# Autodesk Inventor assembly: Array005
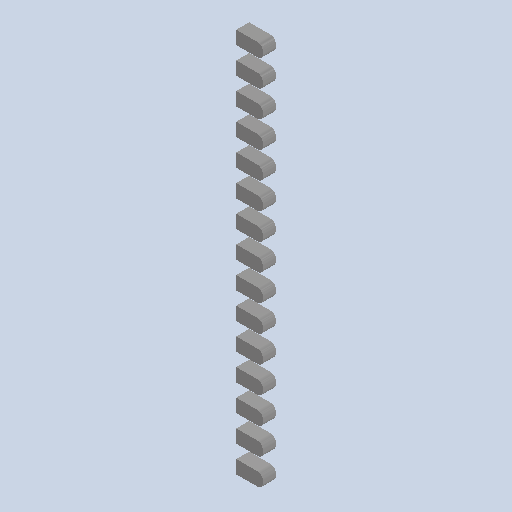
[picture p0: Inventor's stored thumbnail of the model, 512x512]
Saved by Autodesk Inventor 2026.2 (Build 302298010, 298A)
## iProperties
Created: 2026-10
Part Number: Array005
Document SubType Name: Assembly
Designer: mel
Author: mel
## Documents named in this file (16)
- D:\travail\année 2026-2027\1 sti2d IT\poubelle à verre\raspberry-pico-2-microcontroller-rp2350-1.snapshot.5\raspberry_pico_2\raspberry_pico_2\Array005.iam
- D:\travail\année 2026-2027\1 sti2d IT\poubelle à verre\raspberry-pico-2-microcontroller-rp2350-1.snapshot.5\raspberry_pico_2\raspberry_pico_2\Fillet015.ipt
- D:\travail\année 2026-2027\1 sti2d IT\poubelle à verre\raspberry-pico-2-microcontroller-rp2350-1.snapshot.5\raspberry_pico_2\raspberry_pico_2\Fillet016.ipt
- D:\travail\année 2026-2027\1 sti2d IT\poubelle à verre\raspberry-pico-2-microcontroller-rp2350-1.snapshot.5\raspberry_pico_2\raspberry_pico_2\Fillet017.ipt
- D:\travail\année 2026-2027\1 sti2d IT\poubelle à verre\raspberry-pico-2-microcontroller-rp2350-1.snapshot.5\raspberry_pico_2\raspberry_pico_2\Fillet018.ipt
- D:\travail\année 2026-2027\1 sti2d IT\poubelle à verre\raspberry-pico-2-microcontroller-rp2350-1.snapshot.5\raspberry_pico_2\raspberry_pico_2\Fillet019.ipt
- D:\travail\année 2026-2027\1 sti2d IT\poubelle à verre\raspberry-pico-2-microcontroller-rp2350-1.snapshot.5\raspberry_pico_2\raspberry_pico_2\Fillet020.ipt
- D:\travail\année 2026-2027\1 sti2d IT\poubelle à verre\raspberry-pico-2-microcontroller-rp2350-1.snapshot.5\raspberry_pico_2\raspberry_pico_2\Fillet021.ipt
- D:\travail\année 2026-2027\1 sti2d IT\poubelle à verre\raspberry-pico-2-microcontroller-rp2350-1.snapshot.5\raspberry_pico_2\raspberry_pico_2\Fillet022.ipt
- D:\travail\année 2026-2027\1 sti2d IT\poubelle à verre\raspberry-pico-2-microcontroller-rp2350-1.snapshot.5\raspberry_pico_2\raspberry_pico_2\Fillet023.ipt
- D:\travail\année 2026-2027\1 sti2d IT\poubelle à verre\raspberry-pico-2-microcontroller-rp2350-1.snapshot.5\raspberry_pico_2\raspberry_pico_2\Fillet024.ipt
- D:\travail\année 2026-2027\1 sti2d IT\poubelle à verre\raspberry-pico-2-microcontroller-rp2350-1.snapshot.5\raspberry_pico_2\raspberry_pico_2\Fillet025.ipt
- D:\travail\année 2026-2027\1 sti2d IT\poubelle à verre\raspberry-pico-2-microcontroller-rp2350-1.snapshot.5\raspberry_pico_2\raspberry_pico_2\Fillet026.ipt
- D:\travail\année 2026-2027\1 sti2d IT\poubelle à verre\raspberry-pico-2-microcontroller-rp2350-1.snapshot.5\raspberry_pico_2\raspberry_pico_2\Fillet027.ipt
- D:\travail\année 2026-2027\1 sti2d IT\poubelle à verre\raspberry-pico-2-microcontroller-rp2350-1.snapshot.5\raspberry_pico_2\raspberry_pico_2\Fillet028.ipt
- D:\travail\année 2026-2027\1 sti2d IT\poubelle à verre\raspberry-pico-2-microcontroller-rp2350-1.snapshot.5\raspberry_pico_2\raspberry_pico_2\Fillet029.ipt
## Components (15 placed, 15 different names)
1. 2706
2. 2707
3. 2708
4. 2709
5. 2710
6. 2711
7. 2712
8. 2713
9. 2714
10. 2715
11. 2716
12. 2717
13. 2718
14. 2719
15. 2720
